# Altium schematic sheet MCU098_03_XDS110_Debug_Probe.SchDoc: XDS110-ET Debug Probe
size 431 x 279 mm; Date: Not shown in title block; ApprovedBy: Not shown in title block; CheckedBy: Not shown in title block; Author: Not shown in title block; CompanyName: Not shown in title block; DrawnBy: Johnson He; Engineer: Not shown in title block; Organization: Not shown in title block; Address1: Not shown in title block; Address2: Not shown in title block; Address3: Not shown in title block; Address4: Not shown in title block; DocumentNumber: 1; Revision: Use project parameter SCH_Rev; SheetNumber: 3; SheetTotal: 7; PageSetup: Record=PageOptions¦CenterHorizontal=True¦CenterVertical=True¦PrintScale=1.00¦XCorrection=1.00¦YCorrection=1.00¦PrintKind=0¦BorderSize=5000000¦LeftOffset=0¦BottomOffset=0¦Orientation=2¦PaperLength=1000¦PaperWidth=1000¦Scale=100¦PaperSource=15¦PrintQuality=600¦MediaType=1¦DitherType=10¦PaperKind=Letter¦PrintScaleMode=1
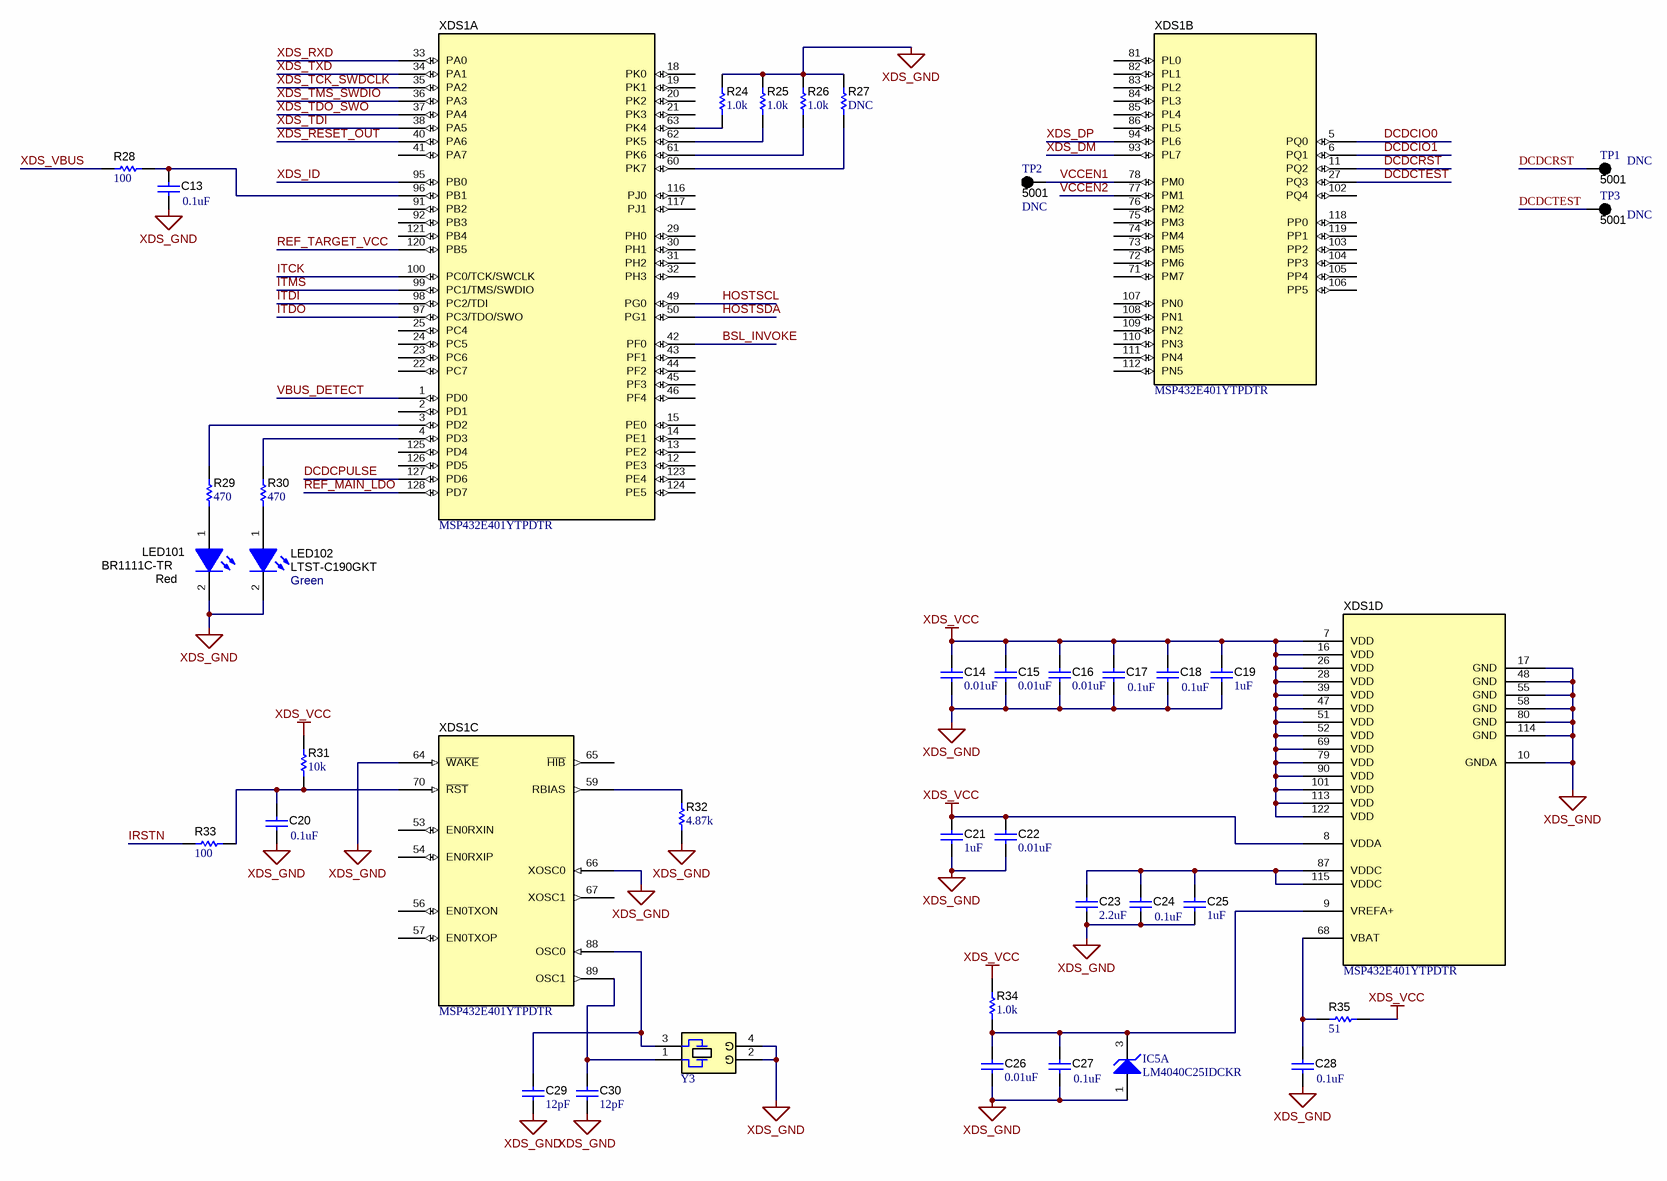
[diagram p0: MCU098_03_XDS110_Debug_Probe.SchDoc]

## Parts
C13  ValueDisplayed: 0.1uF  [0402]  (hidden comment: GRM155R70J104KA01D)
C14  ValueDisplayed: 0.01uF  [0402]  (hidden comment: GRM155R71E103KA01D)
C15  ValueDisplayed: 0.01uF  [0402]  (hidden comment: GRM155R71E103KA01D)
C16  ValueDisplayed: 0.01uF  [0402]  (hidden comment: GRM155R71E103KA01D)
C17  ValueDisplayed: 0.1uF  [0402]  (hidden comment: GRM155R70J104KA01D)
C18  ValueDisplayed: 0.1uF  [0402]  (hidden comment: GRM155R70J104KA01D)
C19  ValueDisplayed: 1uF  [0402]  (hidden comment: C1005X5R1E105K050BC)
C20  ValueDisplayed: 0.1uF  [0402]  (hidden comment: GRM155R70J104KA01D)
C21  ValueDisplayed: 1uF  [0402]  (hidden comment: C1005X5R1E105K050BC)
C22  ValueDisplayed: 0.01uF  [0402]  (hidden comment: GRM155R71E103KA01D)
C23  ValueDisplayed: 2.2uF  [0402]  (hidden comment: GRM155R60J225KE95D)
C24  ValueDisplayed: 0.1uF  [0402]  (hidden comment: GRM155R70J104KA01D)
C25  ValueDisplayed: 1uF  [0402]  (hidden comment: C1005X5R1E105K050BC)
C26  ValueDisplayed: 0.01uF  [0402]  (hidden comment: GRM155R71E103KA01D)
C27  ValueDisplayed: 0.1uF  [0402]  (hidden comment: GRM155R70J104KA01D)
C28  ValueDisplayed: 0.1uF  [0402]  (hidden comment: GRM155R70J104KA01D)
C29  ValueDisplayed: 12pF  [0402]  (hidden comment: GRM1555C1H120JA01D)
C30  ValueDisplayed: 12pF  [0402]  (hidden comment: GRM1555C1H120JA01D)
IC5  LM4040C25IDCKR  [DCK0005A_N]  (part A of 2)
LED101  BR1111C-TR  value Red  [1111C_Red]
LED102  LTST-C190GKT  value Green  [LED_LTST-C190]
R24  ValueDisplayed: 1.0k  [0402]  (hidden comment: CRCW04021K00JNED)
R25  ValueDisplayed: 1.0k  [0402]  (hidden comment: CRCW04021K00JNED)
R26  ValueDisplayed: 1.0k  [0402]  (hidden comment: CRCW04021K00JNED)
R27  ValueDisplayed: DNC  [0402]  (hidden comment: CRCW04021K00JNED)  (no BOM)
R28  ValueDisplayed: 100  [0402]  (hidden comment: CRCW0402100RJNED)
R29  ValueDisplayed: 470  [0402]  (hidden comment: CRCW0402470RJNED)
R30  ValueDisplayed: 470  [0402]  (hidden comment: CRCW0402470RJNED)
R31  ValueDisplayed: 10k  [0402]  (hidden comment: CRCW040210K0JNED)
R32  ValueDisplayed: 4.87k  [0402]  (hidden comment: CRCW04024K87FKED)
R33  ValueDisplayed: 100  [0402]  (hidden comment: CRCW0402100RJNED)
R34  ValueDisplayed: 1.0k  [0402]  (hidden comment: CRCW04021K00JNED)
R35  ValueDisplayed: 51  [0402]  (hidden comment: CRCW040251R0JNED)
TP1  5001  Display: DNC  [Keystone5001]  (no BOM)
TP2  5001  Display: DNC  [Keystone5001]  (no BOM)
TP3  5001  Display: DNC  [Keystone5001]  (no BOM)
XDS1  MSP432E401YTPDTR  [PDT0128A]  (parts A,B,C,D of 4)
Y3  NX3225GA-16.000M-STD-CRG-1  [NDK_NX3225GA]  (value not drawn)

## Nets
XDS_GND: C13.2 C14.2 C15.2 C16.2 C17.2 C18.2 C19.2 C20.2 C21.2 C22.2 C23.2 C24.2 C25.2 C26.2 C27.2 C28.2 C29.2 C30.2 IC5.1(ANODE) LED101.2(K) LED102.2(K) R24.2 R25.2 R26.2 R27.2 R32.1 XDS1.10(GNDA) XDS1.17(GND) XDS1.48(GND) XDS1.55(GND) XDS1.58(GND) XDS1.64(~{WAKE}) XDS1.66(XOSC0) XDS1.80(GND) XDS1.114(GND) Y3.2(GND) Y3.4(GND)
XDS_VCC: C14.1 C15.1 C16.1 C17.1 C18.1 C19.1 C21.1 C22.1 R31.2 R34.2 R35.2 XDS1.7(VDD) XDS1.8(VDDA) XDS1.16(VDD) XDS1.26(VDD) XDS1.28(VDD) XDS1.39(VDD) XDS1.47(VDD) XDS1.51(VDD) XDS1.52(VDD) XDS1.69(VDD) XDS1.79(VDD) XDS1.90(VDD) XDS1.101(VDD) XDS1.113(VDD) XDS1.122(VDD)
BSL_INVOKE: XDS1.42(PF0)
DCDCIO0: XDS1.5(PQ0)
DCDCIO1: XDS1.6(PQ1)
DCDCPULSE: XDS1.127(PD6)
DCDCRST: TP1.1 XDS1.11(PQ2)
DCDCTEST: TP3.1 XDS1.27(PQ3)
HOSTSCL: XDS1.49(PG0)
HOSTSDA: XDS1.50(PG1)
IRSTN: R33.1
ITCK: XDS1.100(PC0/TCK/SWCLK)
ITDI: XDS1.98(PC2/TDI)
ITDO: XDS1.97(PC3/TDO/SWO)
ITMS: XDS1.99(PC1/TMS/SWDIO)
REF_MAIN_LDO: XDS1.128(PD7)
REF_TARGET_VCC: XDS1.120(PB5)
VBUS_DETECT: XDS1.1(PD0)
VCCEN1: TP2.1 XDS1.78(PM0)
VCCEN2: XDS1.77(PM1)
XDS_DM: XDS1.93(PL7)
XDS_DP: XDS1.94(PL6)
XDS_ID: XDS1.95(PB0)
XDS_RESET_OUT: XDS1.40(PA6)
XDS_RXD: XDS1.33(PA0)
XDS_TCK_SWDCLK: XDS1.35(PA2)
XDS_TDI: XDS1.38(PA5)
XDS_TDO_SWO: XDS1.37(PA4)
XDS_TMS_SWDIO: XDS1.36(PA3)
XDS_TXD: XDS1.34(PA1)
XDS_VBUS: R28.1
NetC13_1: C13.1 R28.2 XDS1.96(PB1)
NetC20_1: C20.1 R31.1 R33.2 XDS1.70(~{RST})
NetC23_1: C23.1 C24.1 C25.1 XDS1.87(VDDC) XDS1.115(VDDC)
NetC26_1: C26.1 C27.1 IC5.3(CATHODE) R34.1 XDS1.9(VREFA+)
NetC28_1: C28.1 R35.1 XDS1.68(VBAT)
NetC29_1: C29.1 XDS1.88(OSC0) Y3.3
NetC30_1: C30.1 XDS1.89(OSC1) Y3.1
NetLED101_1: LED101.1(A) R29.1
NetLED102_1: LED102.1(A) R30.1
NetR24_1: R24.1 XDS1.63(PK4)
NetR25_1: R25.1 XDS1.62(PK5)
NetR26_1: R26.1 XDS1.61(PK6)
NetR27_1: R27.1 XDS1.60(PK7)
NetR29_2: R29.2 XDS1.3(PD2)
NetR30_2: R30.2 XDS1.4(PD3)
NetR32_2: R32.2 XDS1.59(RBIAS)

Not connected (* = marked no-connect by the designer): XDS1 2(PD1) 12(PE3) 13(PE2) 14(PE1) 15(PE0) 18(PK0) 19(PK1) 20(PK2) 21(PK3) 22(PC7) 23(PC6) 24(PC5) 25(PC4) 29(PH0) 30(PH1) 31(PH2) 32(PH3) 41(PA7) 43(PF1) 44(PF2) 45(PF3) 46(PF4) 53(EN0RXIN) 54(EN0RXIP) 56(EN0TXON) 57(EN0TXOP) 65(~{HIB}) 67(XOSC1) 71(PM7) 72(PM6) 73(PM5) 74(PM4) 75(PM3) 76(PM2) 81(PL0) 82(PL1) 83(PL2) 84(PL3) 85(PL4) 86(PL5) 91(PB2) 92(PB3) 102(PQ4) 103(PP2) 104(PP3) 105(PP4) 106(PP5) 107(PN0) 108(PN1) 109(PN2) 110(PN3) 111(PN4) 112(PN5) 116(PJ0) 117(PJ1) 118(PP0) 119(PP1) 121(PB4) 123(PE4) 124(PE5) 125(PD4) 126(PD5)

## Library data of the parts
C13 C17 C18 C20 C24 C27 C28 = CMP-0006623-2: CAP, CERM, 0.1 uF, 6.3 V, +/- 10%, X7R, 0402; Manufacturer: MuRata; TaMin_C: -55°C; Polarized: N; SizeAreaWB_mm2: 3; Value1: Unknown; U/M: EA; Value: 0.1uF; TaMax_C: 125°C; SizeZ_mm: 0.6; SizeX_mm: 1; SizeY_mm: 0.5; Value2: 6.3V; Cap_F: 100nF; AEC Category: Q200
C14-C16 C22 C26 = CMP-0006658-2: CAP, CERM, 0.01 uF, 25 V, +/- 10%, X7R, 0402; Manufacturer: MuRata; TaMin_C: -55°C; Polarized: N; SizeAreaWB_mm2: 3; Value1: Unknown; U/M: EA; Value: 0.01uF; TaMax_C: 125°C; SizeZ_mm: 0.6; SizeX_mm: 1; SizeY_mm: 0.5; Value2: 25V; Cap_F: 10nF; AEC Category: Q200
C19 C21 C25 = CMP-0006276-2: CAP, CERM, 1 uF, 25 V, +/- 10%, X5R, 0402; Manufacturer: TDK; TaMin_C: -55°C; Polarized: N; SizeAreaWB_mm2: 3; Value1: Unknown; U/M: EA; Value: 1uF; TaMax_C: 80°C; SizeZ_mm: 0.6; SizeX_mm: 1; SizeY_mm: 0.5; Value2: 25V; Cap_F: 1µF; AEC Category: Q200
C23 = CMP-0006543-2: CAP, CERM, 2.2 uF, 6.3 V, +/- 10%, X5R, 0402; Manufacturer: MuRata; TaMin_C: -55°C; Polarized: N; SizeAreaWB_mm2: 3; Value1: Unknown; U/M: EA; Value: 2.2uF; TaMax_C: 85°C; SizeZ_mm: 0.6; SizeX_mm: 1; SizeY_mm: 0.5; Value2: 6.3V; Cap_F: 2.2µF; AEC Category: Q200
C29 C30 = CMP-0006415-2: CAP, CERM, 12 pF, 50 V, +/- 5%, C0G/NP0, 0402; Manufacturer: MuRata; TaMin_C: -55°C; Polarized: N; SizeAreaWB_mm2: 3; Value1: Unknown; U/M: EA; Value: 12pF; TaMax_C: 125°C; SizeZ_mm: 0.6; SizeX_mm: 1; SizeY_mm: 0.5; Value2: 50V; AEC Category: Q200
IC5 = CMP-0032790-2: Precision Micropower Shunt Voltage Reference, 0.5% accuracy, 2.5 V, 15 ppm / degC, 15 mA, -40 to 85 degC, 5-pin SC70 (DCK), Green (RoHS & no Sb/Br); Manufacturer: Texas Instruments; Min Iz for Regulation(uA): 75; Temp Coeff(Max)(ppm/ degree C): 100; VO(V): 2.5; Temp Coeff(Typ)(ppm/ degree C): 15; Rating: Catalog; Initial Accuracy @ 25/deg C(%): 0.5; AEC Category: Q200; AEC Qualified: N; CompType: IC; SizeAreaWB_mm2: 9.3; SizeArea_mm2: 4.2; SizeX_mm: 2.1; SizeY_mm: 2.0; SizeZ_mm: 1.1
LED101 = CMP-0002972-3: LED, Red, SMD; Manufacturer: Stanley Electric Co., LTD; Power_TotalModule: 57.5mW; Vr_V: 4V; Value1: 0.0575W; Ir_A: 100µA; Io_A: 20mA; Value2: 1.7V; Tjmax_C: 85°C
LED102 = CMP-0002827-3: LED, Green, SMD; Manufacturer: Lite-On; Power_TotalModule: 100mW; Value2: 2.1V; Io_A: 20mA; Value1: 0.1W
R24-R27 R34 = CMP-0026852-1: RES, 1.0 k, 5%, 0.063 W, 0402; Manufacturer: Vishay-Dale; Power_W: 63mW; TempCo: 200 ppm/C; Value_Code: 1k00; U/M: EA; Value: 1.0k; EIA_Code: E24; Res_ohm: 1k; SizeX_mm: 1; SizeY_mm: 0.5; SizeZ_mm: 0.6; Value2: 0.063W; VDC_V: 50V; AEC Category: Q200
R28 = CMP-0026824-3: RES, 100, 5%, 0.063 W, AEC-Q200 Grade 0, 0402; Manufacturer: Vishay-Dale; Power_W: 63mW; TempCo: 200 ppm/C; Value_Code: 100R; Value: 100; EIA_Code: E24; SizeX_mm: 1; SizeY_mm: 0.5; SizeZ_mm: 0.6; Value2: 0.063W; AEC Qualified: Y; VDC_V: 50V; AEC Category: Q200; AEC Grade: 0
R29 R30 = CMP-0026934-2: RES, 470, 5%, 0.063 W, 0402; Manufacturer: Vishay-Dale; Power_W: 63mW; TempCo: 200 ppm/C; Value_Code: 470R; U/M: EA; Value: 470; EIA_Code: E24; SizeX_mm: 1; SizeY_mm: 0.5; SizeZ_mm: 0.6; Value2: 0.063W; VDC_V: 50V; AEC Category: Q200
R31 = CMP-0026825-4: RES, 10 k, 5%, 0.063 W, 0402; Manufacturer: Vishay-Dale; Power_W: 63mW; TempCo: 200 ppm/C; Value_Code: 10k0; U/M: EA; Value: 10k; EIA_Code: E24; SizeX_mm: 1; SizeY_mm: 0.5; SizeZ_mm: 0.6; Value2: 0.063W; VDC_V: 50V; AEC Category: Q200
R32 = CMP-0026413-2: RES, 4.87 k, 1%, 0.063 W, AEC-Q200 Grade 0, 0402; Manufacturer: Vishay-Dale; Power_W: 63mW; TempCo: 100 ppm/C; Value_Code: 4k87; Value: 4.87k; EIA_Code: E96; SizeX_mm: 1; SizeY_mm: 0.5; SizeZ_mm: 0.6; Value2: 0.063W; AEC Qualified: Y; VDC_V: 50V; AEC Category: Q200; AEC Grade: 0
R33 = CMP-0026824-1: RES, 100, 5%, 0.063 W, 0402; Manufacturer: Vishay-Dale; Power_W: 63mW; TempCo: 200 ppm/C; Value_Code: 100R; U/M: EA; Value: 100; EIA_Code: E24; SizeX_mm: 1; SizeY_mm: 0.5; SizeZ_mm: 0.6; Value2: 0.063W; VDC_V: 50V; AEC Category: Q200
R35 = CMP-0026946-3: RES, 51, 5%, 0.063 W, AEC-Q200 Grade 0, 0402; Manufacturer: Vishay-Dale; Power_W: 63mW; TempCo: 200 ppm/C; Value_Code: 51R0; Value: 51; EIA_Code: E24; SizeX_mm: 1; SizeY_mm: 0.5; SizeZ_mm: 0.6; Value2: 0.063W; AEC Qualified: Y; VDC_V: 50V; AEC Category: Q200; AEC Grade: 0
TP1-TP3 = CMP-0055138-1: Test Point, Miniature, Black, TH; Manufacturer: Keystone; CNHeader: FALSE; Green_Lifecycle: Active; Green_REACh: Passed; ContactFinish: Silver; CT: TRUE
XDS1 = CMP-0077954-1: MSP432E401YTPDT, PDT0128A (TQFP-128); Alternate Manufacturer: Texas Instruments; SizeAreaWB_mm2: 324; SizeZ_mm: 1.2; SizeX_mm: 16; SizeArea_mm2: 256; CompType: IC; AEC Qualified: N; AEC Category: Q200
Y3 = CMP-0004635-1: Crystal, 16 MHz, 8pF, SMD; Manufacturer: NDK; TaMax_C: 70°C; TaMin_C: -10°C; Frequency Stability: +/-30ppm; U/M: EA; Frequency_Fixed: 16MHz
